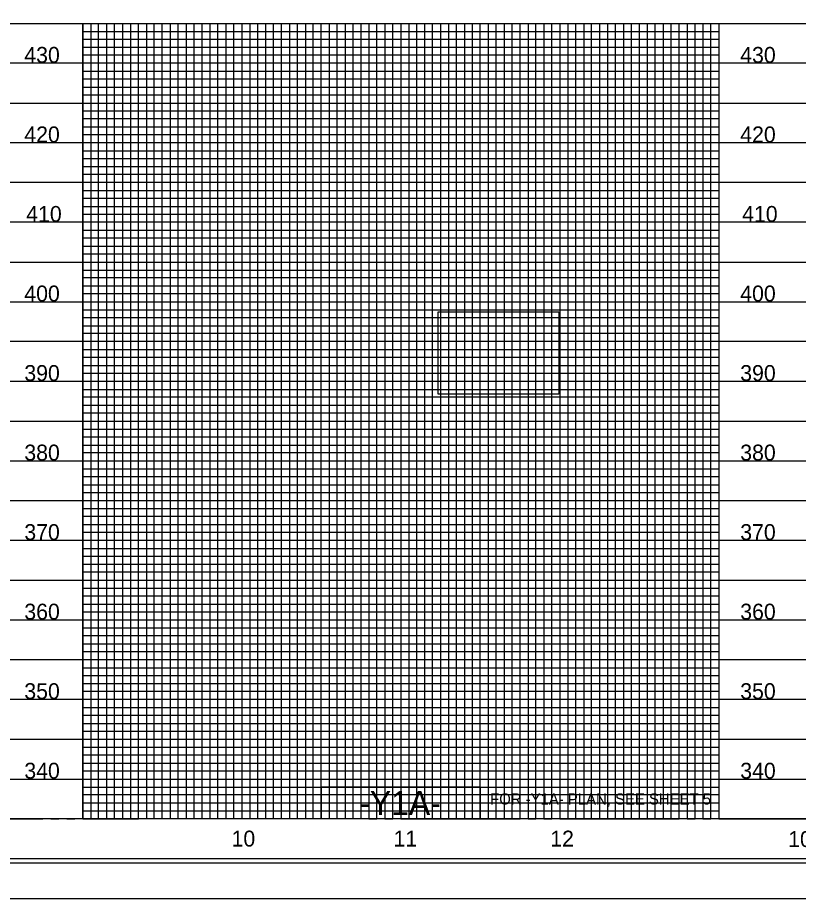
# Model space of a CAD drawing. Extents: x 1629737 to 1631945, y 1172886 to 1173986.
# Drawn here: x 1630513 to 1631004, y 1172886 to 1173440 of the extents above; entities that cross this region are included whole.
import ezdxf

# ---------------------------------------------------------------- set-up
doc = ezdxf.new("R2010")
doc.units = 0
for name, color, linetype in [('Exist Vertical Profile Horizontal Axis Label Major', 7, 'Continuous'), ('Exist Vertical Profile Vertical Axis Label', 7, 'Continuous'), ('Prop Grid Mask', 7, 'Continuous'), ('Sheet Data Field CELL', 7, 'Continuous'), ('Sheet Layout Profile Border Port 2', 7, 'Continuous'), ('Sheet Plot Border Inside CELL', 7, 'Continuous'), ('Sheet Plot Border Outside CELL', 7, 'Continuous'), ('Sheet Profile CELL', 7, 'Continuous'), ('Sheet Profile Grid Major CELL', 7, 'Continuous'), ('Sheet Profile Grid Middle CELL', 7, 'Continuous'), ('Sheet Profile Grid Minor CELL', 7, 'Continuous')]:
    doc.layers.add(name, color=color, linetype=linetype)

msp = doc.modelspace()

# ---------------------------------------------------------------- linework, layer by layer
at = {"layer": 'Prop Grid Mask'}
for points in [[(1630777.82, 1173254.59), (1630853.69, 1173254.59), (1630853.69, 1173202.83), (1630777.82, 1173202.83)], [(1630804.31, 1172960.94), (1630954.31, 1172960.94), (1630954.31, 1172935.94), (1630804.31, 1172935.94)], [(1630704.31, 1172955.94), (1630804.31, 1172955.94), (1630804.31, 1172935.94), (1630704.31, 1172935.94)], [(1630704.31, 1172955.94), (1630804.31, 1172955.94), (1630804.31, 1172935.94), (1630704.31, 1172935.94)]]:
    msp.add_lwpolyline(points, close=True, dxfattribs=at)
at = {"layer": 'Sheet Layout Profile Border Port 2'}
msp.add_lwpolyline([(1630554.31, 1173435.94), (1630954.31, 1173435.94), (1630954.31, 1172935.94), (1630804.31, 1172935.94), (1630804.31, 1172955.94), (1630704.31, 1172955.94), (1630704.31, 1172935.94), (1630554.31, 1172935.94)], close=True, dxfattribs=at)
at = {"layer": 'Sheet Plot Border Inside CELL'}
msp.add_lwpolyline([(1629750.31, 1172908.39), (1631416.81, 1172908.39), (1631416.81, 1173963.49), (1629750.31, 1173963.49)], close=True, dxfattribs=at)
at = {"layer": 'Sheet Plot Border Outside CELL'}
msp.add_lwpolyline([(1629737.31, 1172885.94), (1631421.31, 1172885.94), (1631421.31, 1173985.94), (1629737.31, 1173985.94)], close=True, dxfattribs=at)
at = {"layer": 'Sheet Profile CELL'}
for p, q in [((1629904.31, 1173435.94), (1631404.31, 1173435.94)), ((1631404.31, 1172935.94), (1629904.31, 1172935.94)), ((1629904.31, 1172910.94), (1631404.31, 1172910.94))]:
    msp.add_line(p, q, dxfattribs=at)
msp.add_lwpolyline([(1631404.31, 1173960.94), (1629904.31, 1173960.94), (1629904.31, 1172910.94), (1631404.31, 1172910.94)], close=True, dxfattribs=at)
at = {"layer": 'Sheet Profile Grid Major CELL'}
for p, q in [((1630504.31, 1173435.94), (1630554.31, 1173435.94)), ((1630504.31, 1173435.94), (1630554.31, 1173435.94)), ((1630554.31, 1173435.94), (1630554.31, 1172935.94)), ((1630604.31, 1173435.94), (1630654.31, 1173435.94)), ((1630604.31, 1172935.94), (1630604.31, 1173435.94)), ((1630604.31, 1173435.94), (1630654.31, 1173435.94)), ((1630654.31, 1173435.94), (1630654.31, 1172935.94)), ((1630704.31, 1173435.94), (1630754.31, 1173435.94)), ((1630704.31, 1172935.94), (1630704.31, 1173435.94)), ((1630704.31, 1173435.94), (1630754.31, 1173435.94)), ((1630754.31, 1173435.94), (1630754.31, 1172935.94)), ((1630804.31, 1173435.94), (1630854.31, 1173435.94)), ((1630804.31, 1172935.94), (1630804.31, 1173435.94)), ((1630804.31, 1173435.94), (1630854.31, 1173435.94)), ((1630854.31, 1173435.94), (1630854.31, 1172935.94)), ((1630904.31, 1173435.94), (1630954.31, 1173435.94)), ((1630904.31, 1172935.94), (1630904.31, 1173435.94)), ((1630904.31, 1173435.94), (1630954.31, 1173435.94)), ((1630954.31, 1173435.94), (1630954.31, 1172935.94)), ((1630554.31, 1172935.94), (1630584.31, 1172935.94)), ((1630754.31, 1172935.94), (1630804.31, 1172935.94)), ((1630854.31, 1172935.94), (1630904.31, 1172935.94)), ((1630954.31, 1172935.94), (1631004.31, 1172935.94))]:
    msp.add_line(p, q, dxfattribs=at)
for points in [[(1631404.31, 1173410.94), (1629904.31, 1173410.94)], [(1631404.31, 1173360.94), (1629904.31, 1173360.94)], [(1631404.31, 1173310.94), (1629904.31, 1173310.94), (1629904.31, 1173260.94), (1631404.31, 1173260.94)], [(1631404.31, 1173210.94), (1629904.31, 1173210.94), (1629904.31, 1173160.94), (1631404.31, 1173160.94)], [(1631404.31, 1173110.94), (1629904.31, 1173110.94), (1629904.31, 1173060.94), (1631404.31, 1173060.94)], [(1631404.31, 1173010.94), (1629904.31, 1173010.94), (1629904.31, 1173010.94), (1629904.31, 1172960.94), (1631404.31, 1172960.94)], [(1631404.31, 1172935.94), (1629904.31, 1172935.94)]]:
    msp.add_lwpolyline(points, dxfattribs=at)
at = {"layer": 'Sheet Profile Grid Middle CELL'}
for p, q in [((1630529.31, 1173435.94), (1630579.31, 1173435.94)), ((1630579.31, 1173435.94), (1630579.31, 1172935.94)), ((1630629.31, 1172935.94), (1630629.31, 1173435.94)), ((1630629.31, 1173435.94), (1630679.31, 1173435.94)), ((1630679.31, 1172935.94), (1630679.31, 1173435.94)), ((1630729.31, 1172935.94), (1630729.31, 1173435.94)), ((1630729.31, 1173435.94), (1630779.31, 1173435.94)), ((1630779.31, 1173435.94), (1630779.31, 1172935.94)), ((1630829.31, 1172935.94), (1630829.31, 1173435.94)), ((1630829.31, 1173435.94), (1630879.31, 1173435.94)), ((1630879.31, 1173435.94), (1630879.31, 1172935.94)), ((1630929.31, 1172935.94), (1630929.31, 1173435.94)), ((1630929.31, 1173435.94), (1630979.31, 1173435.94)), ((1630479.31, 1172935.94), (1630529.31, 1172935.94)), ((1630529.31, 1172935.94), (1630529.31, 1172935.94)), ((1630779.31, 1172935.94), (1630829.31, 1172935.94)), ((1630879.31, 1172935.94), (1630929.31, 1172935.94)), ((1630979.31, 1172935.94), (1631029.31, 1172935.94))]:
    msp.add_line(p, q, dxfattribs=at)
for points in [[(1629904.31, 1173385.94), (1631404.31, 1173385.94)], [(1631404.31, 1173335.94), (1629904.31, 1173335.94), (1629904.31, 1173285.94), (1631404.31, 1173285.94)], [(1631404.31, 1173235.94), (1629904.31, 1173235.94), (1629904.31, 1173185.94), (1631404.31, 1173185.94)], [(1631404.31, 1173135.94), (1629904.31, 1173135.94), (1629904.31, 1173085.94), (1631404.31, 1173085.94)], [(1631404.31, 1173035.94), (1629904.31, 1173035.94), (1629904.31, 1172985.94), (1631404.31, 1172985.94)], [(1631404.31, 1172935.94), (1629904.31, 1172935.94)]]:
    msp.add_lwpolyline(points, dxfattribs=at)
at = {"layer": 'Sheet Profile Grid Minor CELL'}
for p, q in [((1630514.31, 1173435.94), (1630519.31, 1173435.94)), ((1630524.31, 1173435.94), (1630534.31, 1173435.94)), ((1630539.31, 1173435.94), (1630544.31, 1173435.94)), ((1630549.31, 1173435.94), (1630559.31, 1173435.94)), ((1630559.31, 1173435.94), (1630559.31, 1172935.94)), ((1630564.31, 1172935.94), (1630564.31, 1173435.94)), ((1630564.31, 1173435.94), (1630569.31, 1173435.94)), ((1630569.31, 1173435.94), (1630569.31, 1172935.94)), ((1630574.31, 1172935.94), (1630574.31, 1173435.94)), ((1630574.31, 1173435.94), (1630584.31, 1173435.94)), ((1630584.31, 1173435.94), (1630584.31, 1172935.94)), ((1630589.31, 1172935.94), (1630589.31, 1173435.94)), ((1630589.31, 1173435.94), (1630594.31, 1173435.94)), ((1630594.31, 1173435.94), (1630594.31, 1172935.94)), ((1630599.31, 1172935.94), (1630599.31, 1173435.94)), ((1630599.31, 1173435.94), (1630609.31, 1173435.94)), ((1630609.31, 1173435.94), (1630609.31, 1172935.94)), ((1630614.31, 1172935.94), (1630614.31, 1173435.94)), ((1630614.31, 1173435.94), (1630619.31, 1173435.94)), ((1630619.31, 1173435.94), (1630619.31, 1172935.94)), ((1630624.31, 1172935.94), (1630624.31, 1173435.94)), ((1630624.31, 1173435.94), (1630634.31, 1173435.94)), ((1630634.31, 1173435.94), (1630634.31, 1172935.94)), ((1630649.31, 1172935.94), (1630649.31, 1173435.94)), ((1630649.31, 1173435.94), (1630659.31, 1173435.94)), ((1630659.31, 1173435.94), (1630659.31, 1172935.94)), ((1630664.31, 1172935.94), (1630664.31, 1173435.94)), ((1630669.31, 1173435.94), (1630669.31, 1172935.94)), ((1630674.31, 1172935.94), (1630674.31, 1173435.94)), ((1630684.31, 1173435.94), (1630684.31, 1172935.94)), ((1630689.31, 1172935.94), (1630689.31, 1173435.94)), ((1630694.31, 1173435.94), (1630694.31, 1172935.94)), ((1630699.31, 1173435.94), (1630709.31, 1173435.94)), ((1630699.31, 1172935.94), (1630699.31, 1173435.94)), ((1630709.31, 1173435.94), (1630709.31, 1172935.94)), ((1630714.31, 1172935.94), (1630714.31, 1173435.94)), ((1630714.31, 1173435.94), (1630719.31, 1173435.94)), ((1630719.31, 1173435.94), (1630719.31, 1172935.94)), ((1630724.31, 1172935.94), (1630724.31, 1173435.94)), ((1630724.31, 1173435.94), (1630734.31, 1173435.94)), ((1630734.31, 1173435.94), (1630734.31, 1172935.94)), ((1630739.31, 1172935.94), (1630739.31, 1173435.94)), ((1630739.31, 1173435.94), (1630744.31, 1173435.94)), ((1630744.31, 1173435.94), (1630744.31, 1172935.94)), ((1630749.31, 1172935.94), (1630749.31, 1173435.94)), ((1630749.31, 1173435.94), (1630759.31, 1173435.94)), ((1630759.31, 1173435.94), (1630759.31, 1172935.94)), ((1630764.31, 1172935.94), (1630764.31, 1173435.94)), ((1630764.31, 1173435.94), (1630769.31, 1173435.94)), ((1630769.31, 1173435.94), (1630769.31, 1172935.94)), ((1630774.31, 1172935.94), (1630774.31, 1173435.94)), ((1630774.31, 1173435.94), (1630784.31, 1173435.94)), ((1630784.31, 1173435.94), (1630784.31, 1172935.94)), ((1630789.31, 1172935.94), (1630789.31, 1173435.94)), ((1630789.31, 1173435.94), (1630794.31, 1173435.94)), ((1630794.31, 1173435.94), (1630794.31, 1172935.94)), ((1630799.31, 1172935.94), (1630799.31, 1173435.94)), ((1630799.31, 1173435.94), (1630809.31, 1173435.94)), ((1630809.31, 1173435.94), (1630809.31, 1172935.94)), ((1630814.31, 1172935.94), (1630814.31, 1173435.94)), ((1630814.31, 1173435.94), (1630819.31, 1173435.94)), ((1630819.31, 1173435.94), (1630819.31, 1172935.94)), ((1630824.31, 1172935.94), (1630824.31, 1173435.94)), ((1630824.31, 1173435.94), (1630834.31, 1173435.94)), ((1630834.31, 1173435.94), (1630834.31, 1172935.94)), ((1630839.31, 1172935.94), (1630839.31, 1173435.94)), ((1630839.31, 1173435.94), (1630844.31, 1173435.94)), ((1630844.31, 1173435.94), (1630844.31, 1172935.94)), ((1630849.31, 1172935.94), (1630849.31, 1173435.94)), ((1630849.31, 1173435.94), (1630859.31, 1173435.94)), ((1630859.31, 1173435.94), (1630859.31, 1172935.94)), ((1630864.31, 1172935.94), (1630864.31, 1173435.94)), ((1630864.31, 1173435.94), (1630869.31, 1173435.94)), ((1630869.31, 1173435.94), (1630869.31, 1172935.94)), ((1630874.31, 1172935.94), (1630874.31, 1173435.94)), ((1630874.31, 1173435.94), (1630884.31, 1173435.94)), ((1630884.31, 1173435.94), (1630884.31, 1172935.94)), ((1630889.31, 1172935.94), (1630889.31, 1173435.94)), ((1630889.31, 1173435.94), (1630894.31, 1173435.94)), ((1630894.31, 1173435.94), (1630894.31, 1172935.94)), ((1630899.31, 1172935.94), (1630899.31, 1173435.94)), ((1630899.31, 1173435.94), (1630909.31, 1173435.94)), ((1630909.31, 1173435.94), (1630909.31, 1172935.94)), ((1630914.31, 1172935.94), (1630914.31, 1173435.94)), ((1630914.31, 1173435.94), (1630919.31, 1173435.94)), ((1630919.31, 1173435.94), (1630919.31, 1172935.94)), ((1630924.31, 1172935.94), (1630924.31, 1173435.94)), ((1630924.31, 1173435.94), (1630934.31, 1173435.94)), ((1630934.31, 1173435.94), (1630934.31, 1172935.94)), ((1630939.31, 1172935.94), (1630939.31, 1173435.94)), ((1630939.31, 1173435.94), (1630944.31, 1173435.94)), ((1630944.31, 1173435.94), (1630944.31, 1172935.94)), ((1630949.31, 1172935.94), (1630949.31, 1173435.94)), ((1630949.31, 1173435.94), (1630959.31, 1173435.94)), ((1630964.31, 1173435.94), (1630969.31, 1173435.94)), ((1630974.31, 1173435.94), (1630984.31, 1173435.94)), ((1630989.31, 1173435.94), (1630994.31, 1173435.94)), ((1630999.31, 1173435.94), (1631009.31, 1173435.94)), ((1630554.31, 1173430.94), (1630954.31, 1173430.94)), ((1630954.31, 1173425.94), (1630554.31, 1173425.94)), ((1630554.31, 1173420.94), (1630954.31, 1173420.94)), ((1630954.31, 1173415.94), (1630554.31, 1173415.94)), ((1630554.31, 1173405.94), (1630954.31, 1173405.94)), ((1630954.31, 1173400.94), (1630554.31, 1173400.94)), ((1630554.31, 1173395.94), (1630954.31, 1173395.94)), ((1630954.31, 1173390.94), (1630554.31, 1173390.94)), ((1630554.31, 1173380.94), (1630954.31, 1173380.94)), ((1630954.31, 1173375.94), (1630554.31, 1173375.94)), ((1630554.31, 1173370.94), (1630954.31, 1173370.94)), ((1630954.31, 1173365.94), (1630554.31, 1173365.94)), ((1630554.31, 1173355.94), (1630954.31, 1173355.94)), ((1630954.31, 1173350.94), (1630554.31, 1173350.94)), ((1630554.31, 1173345.94), (1630954.31, 1173345.94)), ((1630954.31, 1173340.94), (1630554.31, 1173340.94)), ((1630554.31, 1173330.94), (1630954.31, 1173330.94)), ((1630954.31, 1173325.94), (1630554.31, 1173325.94)), ((1630554.31, 1173320.94), (1630954.31, 1173320.94)), ((1630954.31, 1173315.94), (1630554.31, 1173315.94)), ((1630554.31, 1173305.94), (1630954.31, 1173305.94)), ((1630954.31, 1173300.94), (1630554.31, 1173300.94)), ((1630554.31, 1173295.94), (1630954.31, 1173295.94)), ((1630954.31, 1173290.94), (1630554.31, 1173290.94)), ((1630554.31, 1173280.94), (1630954.31, 1173280.94)), ((1630954.31, 1173275.94), (1630554.31, 1173275.94)), ((1630554.31, 1173270.94), (1630954.31, 1173270.94)), ((1630954.31, 1173265.94), (1630554.31, 1173265.94)), ((1630554.31, 1173255.94), (1630954.31, 1173255.94)), ((1630954.31, 1173250.94), (1630554.31, 1173250.94)), ((1630554.31, 1173245.94), (1630954.31, 1173245.94)), ((1630954.31, 1173240.98), (1630554.31, 1173241.02)), ((1630554.31, 1173230.94), (1630954.31, 1173230.94)), ((1630954.31, 1173225.94), (1630554.31, 1173225.94)), ((1630554.31, 1173220.94), (1630954.31, 1173220.94)), ((1630954.31, 1173215.94), (1630554.31, 1173215.94)), ((1630554.31, 1173205.94), (1630954.31, 1173205.94)), ((1630954.31, 1173200.94), (1630554.31, 1173200.94)), ((1630554.31, 1173195.94), (1630954.31, 1173195.94)), ((1630954.31, 1173190.94), (1630554.31, 1173190.94)), ((1630554.31, 1173180.94), (1630954.31, 1173180.94)), ((1630954.31, 1173175.94), (1630554.31, 1173175.94)), ((1630554.31, 1173170.94), (1630954.31, 1173170.94)), ((1630954.31, 1173165.94), (1630554.31, 1173165.94)), ((1630554.31, 1173155.94), (1630954.31, 1173155.94)), ((1630954.31, 1173150.94), (1630554.31, 1173150.94)), ((1630554.31, 1173145.94), (1630954.31, 1173145.94)), ((1630954.31, 1173140.94), (1630554.31, 1173140.94)), ((1630554.31, 1173130.94), (1630954.31, 1173130.94)), ((1630954.31, 1173125.94), (1630554.31, 1173125.94)), ((1630554.31, 1173120.94), (1630954.31, 1173120.94)), ((1630954.31, 1173115.94), (1630554.31, 1173115.94)), ((1630554.31, 1173105.94), (1630954.31, 1173105.94)), ((1630954.31, 1173100.94), (1630554.31, 1173100.94)), ((1630554.31, 1173095.94), (1630954.31, 1173095.94)), ((1630954.31, 1173090.94), (1630554.31, 1173090.94)), ((1630554.31, 1173080.94), (1630954.31, 1173080.94)), ((1630954.31, 1173075.94), (1630554.31, 1173075.94)), ((1630554.31, 1173070.94), (1630954.31, 1173070.94)), ((1630954.31, 1173065.94), (1630554.31, 1173065.94)), ((1630554.31, 1173055.94), (1630954.31, 1173055.94)), ((1630954.31, 1173050.94), (1630554.31, 1173050.94)), ((1630554.31, 1173045.94), (1630954.31, 1173045.94)), ((1630954.31, 1173040.94), (1630554.31, 1173040.94)), ((1630554.31, 1173030.94), (1630954.31, 1173030.94)), ((1630954.31, 1173025.94), (1630554.31, 1173025.94)), ((1630554.31, 1173020.94), (1630954.31, 1173020.94)), ((1630954.31, 1173015.94), (1630554.31, 1173015.94)), ((1630554.31, 1173005.94), (1630954.31, 1173005.94)), ((1630954.31, 1173000.94), (1630554.31, 1173000.94)), ((1630554.31, 1172995.94), (1630954.31, 1172995.94)), ((1630954.31, 1172990.94), (1630554.31, 1172990.94)), ((1630554.31, 1172980.94), (1630954.31, 1172980.94)), ((1630954.31, 1172975.94), (1630554.31, 1172975.94)), ((1630554.31, 1172970.94), (1630954.31, 1172970.94)), ((1630954.31, 1172965.94), (1630554.31, 1172965.94)), ((1630554.31, 1172955.94), (1630954.31, 1172955.94)), ((1630954.31, 1172950.94), (1630554.31, 1172950.94)), ((1630734.31, 1172950.94), (1630704.31, 1172950.94)), ((1630554.31, 1172945.94), (1630954.31, 1172945.94)), ((1630704.31, 1172945.94), (1630734.31, 1172945.94)), ((1630509.31, 1172935.94), (1630514.31, 1172935.94)), ((1630519.31, 1172935.94), (1630524.31, 1172935.94)), ((1630534.31, 1172935.94), (1630539.31, 1172935.94)), ((1630544.31, 1172935.94), (1630549.31, 1172935.94)), ((1630554.31, 1172940.94), (1630954.31, 1172940.94)), ((1630559.31, 1172935.94), (1630564.31, 1172935.94)), ((1630569.31, 1172935.94), (1630574.31, 1172935.94)), ((1630584.31, 1172935.94), (1630589.31, 1172935.94)), ((1630704.31, 1172940.94), (1630734.31, 1172940.94)), ((1630734.31, 1172935.94), (1630739.31, 1172935.94)), ((1630744.31, 1172935.94), (1630749.31, 1172935.94)), ((1630759.31, 1172935.94), (1630764.31, 1172935.94)), ((1630769.31, 1172935.94), (1630774.31, 1172935.94)), ((1630784.31, 1172935.94), (1630789.31, 1172935.94)), ((1630794.31, 1172935.94), (1630799.31, 1172935.94)), ((1630809.31, 1172935.94), (1630814.31, 1172935.94)), ((1630819.31, 1172935.94), (1630824.31, 1172935.94)), ((1630834.31, 1172935.94), (1630839.31, 1172935.94)), ((1630844.31, 1172935.94), (1630849.31, 1172935.94)), ((1630859.31, 1172935.94), (1630864.31, 1172935.94)), ((1630869.31, 1172935.94), (1630874.31, 1172935.94)), ((1630884.31, 1172935.94), (1630889.31, 1172935.94)), ((1630894.31, 1172935.94), (1630899.31, 1172935.94)), ((1630909.31, 1172935.94), (1630914.31, 1172935.94)), ((1630919.31, 1172935.94), (1630924.31, 1172935.94)), ((1630934.31, 1172935.94), (1630939.31, 1172935.94)), ((1630944.31, 1172935.94), (1630949.31, 1172935.94)), ((1630959.31, 1172935.94), (1630964.31, 1172935.94)), ((1630969.31, 1172935.94), (1630974.31, 1172935.94)), ((1630984.31, 1172935.94), (1630989.31, 1172935.94)), ((1630994.31, 1172935.94), (1630999.31, 1172935.94))]:
    msp.add_line(p, q, dxfattribs=at)
msp.add_lwpolyline([(1630639.31, 1172935.94), (1630639.31, 1173435.94), (1630644.31, 1173435.94), (1630644.31, 1172935.94)], dxfattribs=at)

# ---------------------------------------------------------------- texts
at = {"layer": 'Exist Vertical Profile Horizontal Axis Label Major'}
for s, p in [('10', (1630647.9, 1172918.52)), ('11', (1630749.74, 1172918.52)), ('12', (1630848.29, 1172918.52)), ('10', (1630997.9, 1172918.23))]:
    msp.add_text(s, height=10, dxfattribs=at).set_placement(p)
at = {"layer": 'Exist Vertical Profile Vertical Axis Label'}
for s, p in [('430', (1630517.58, 1173411.19)), ('430', (1630967.75, 1173411.19)), ('420', (1630517.58, 1173361.19)), ('420', (1630967.75, 1173361.19)), ('410', (1630518.78, 1173311.19)), ('410', (1630968.94, 1173311.19)), ('400', (1630517.58, 1173261.19)), ('400', (1630967.75, 1173261.19)), ('390', (1630517.58, 1173211.19)), ('390', (1630967.75, 1173211.19)), ('380', (1630517.58, 1173161.19)), ('380', (1630967.75, 1173161.19)), ('370', (1630517.58, 1173111.19)), ('370', (1630967.75, 1173111.19)), ('360', (1630517.58, 1173061.19)), ('360', (1630967.75, 1173061.19)), ('350', (1630517.58, 1173011.19)), ('350', (1630967.75, 1173011.19)), ('340', (1630517.58, 1172961.19)), ('340', (1630967.75, 1172961.19))]:
    msp.add_text(s, height=10, dxfattribs=at).set_placement(p)
at = {"layer": 'Sheet Data Field CELL'}
for s, height, p in [('-Y1A-', 15, (1630728.18, 1172938.44)), ('FOR -Y1A- PLAN, SEE SHEET 5', 7, (1630810.48, 1172944.94))]:
    msp.add_text(s, height=height, rotation=360, dxfattribs=at).set_placement(p)

doc.saveas('drawing.dxf')
